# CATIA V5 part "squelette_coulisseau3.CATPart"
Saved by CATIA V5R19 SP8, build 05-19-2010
Part number: squelette_coulisseau3
Publications: "Plan.1", "Droite.1"
Bounding box of the stored display mesh (mm): x 0 to 0, y -28 to 0, z -27.23 to 8
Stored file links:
  C:\Users\ThinkMotion\Desktop\EU_thinkMotion\iao\IAO_MMS_Groupe3\pmayet\pmayet_avant_optimisation\pmayet_avant_optimisation\squelette_coulisseau3.CATPart
  C:\Users\ThinkMotion\Desktop\EU_thinkMotion\iao\IAO_MMS_Groupe3\pmayet\pmayet_avant_optimisation\pmayet_avant_optimisation\squelette.CATProduct
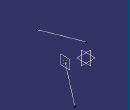
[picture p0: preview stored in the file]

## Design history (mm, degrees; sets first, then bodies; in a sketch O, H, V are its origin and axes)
Set1
  Point1 "Point3": linked copy from another document
  Line1: linked copy from another document
Set2
  Plane1: type OffsetPt, RefPlane yz-plane, RefPoint Point1
  Line2: type Angle, RefPoint Point1, Curve Line1, Start 0, End 20, Angle 90
Body1 (main body)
